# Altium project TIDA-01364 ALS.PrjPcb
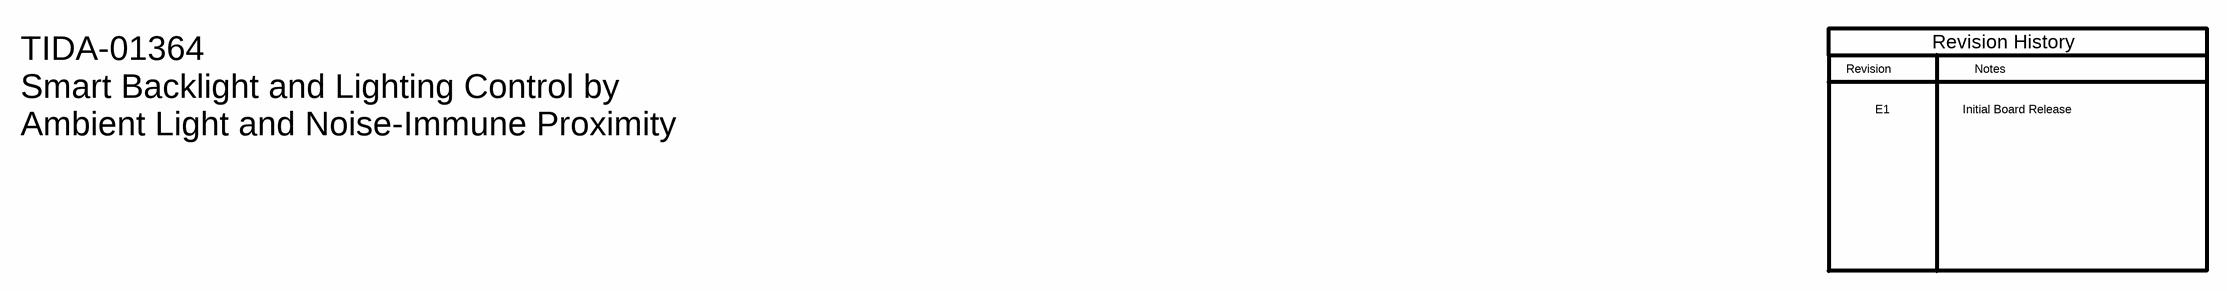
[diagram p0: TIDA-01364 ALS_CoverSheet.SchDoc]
TID: TIDA-01364; TechSupport: http://www.ti.com/support; SCH_Rev: A; PRJ_Title: TIDA-01364 Backlight Control and Proximity Sensing; PRJ_Number: TIDA-01364; PRJ_Engineer: Jarrod Krebs; PRJ_Customer: Public Release; PCB_Rev: A; EVM_Orderable: N/A; CopyrightYear: 2016
5 sheets, 139 parts. Net scope: global (net labels, ports and power ports of the same name join across sheets).
Board file: TIDA-01364 ALS_TID.PcbDoc
Sheets:
  TIDA-01364 ALS_CoverSheet.SchDoc
  TIDA-01364 ALS_Sheet1.SchDoc
  TIDA-01364 ALS_Sheet2.SchDoc
  TIDA-01364 ALS_Sheet3.SchDoc
  TIDA-01364 ALS_TID_Hardware.SchDoc

## Sheet TIDA-01364 ALS_CoverSheet.SchDoc: Cover Sheet
size 431 x 279 mm; Date: Not shown in title block; ApprovedBy: Not shown in title block; CheckedBy: Not shown in title block; Author: Not shown in title block; CompanyName: Not shown in title block; DrawnBy: Jarrod Krebs; Engineer: Not shown in title block; Organization: Not shown in title block; Address1: Not shown in title block; Address2: Not shown in title block; Address3: Not shown in title block; Address4: Not shown in title block; DocumentNumber: 1; Revision: Use project parameter SCH_Rev; SheetNumber: 1; SheetTotal: 5; PageSetup: Record=PageOptions¦CenterHorizontal=True¦CenterVertical=True¦PrintScale=1.00¦XCorrection=1.00¦YCorrection=1.00¦PrintKind=0¦BorderSize=5000000¦LeftOffset=0¦BottomOffset=0¦Orientation=2¦PaperLength=1000¦PaperWidth=1000¦Scale=100¦PaperSource=15¦PrintQuality=-3¦MediaType=1¦DitherType=10¦PrintScaleMode=1¦PaperKind=Letter¦PaperIndex=1

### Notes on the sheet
- Revision
- Notes
- Revision History
- E1
- Initial Board Release
- TIDA-01364
  Smart Backlight and Lighting Control by
  Ambient Light and Noise-Immune Proximity
  Sensor Reference Design

## Sheet TIDA-01364 ALS_Sheet1.SchDoc: Power and Display
size 431 x 279 mm; Date: Not shown in title block; ApprovedBy: Not shown in title block; CheckedBy: Not shown in title block; Author: Not shown in title block; CompanyName: Not shown in title block; DrawnBy: Jarrod Krebs; Engineer: Not shown in title block; Organization: Not shown in title block; Address1: Not shown in title block; Address2: Not shown in title block; Address3: Not shown in title block; Address4: Not shown in title block; DocumentNumber: 3; Revision: Use project parameter SCH_Rev; SheetNumber: 3; SheetTotal: 5; PageSetup: Record=PageOptions¦CenterHorizontal=True¦CenterVertical=True¦PrintScale=1.00¦XCorrection=1.00¦YCorrection=1.00¦PrintKind=0¦BorderSize=5000000¦LeftOffset=0¦BottomOffset=0¦Orientation=2¦PaperLength=1000¦PaperWidth=1000¦Scale=100¦PaperSource=15¦PrintQuality=-3¦MediaType=1¦DitherType=10¦PrintScaleMode=1¦PaperKind=Letter¦PaperIndex=1
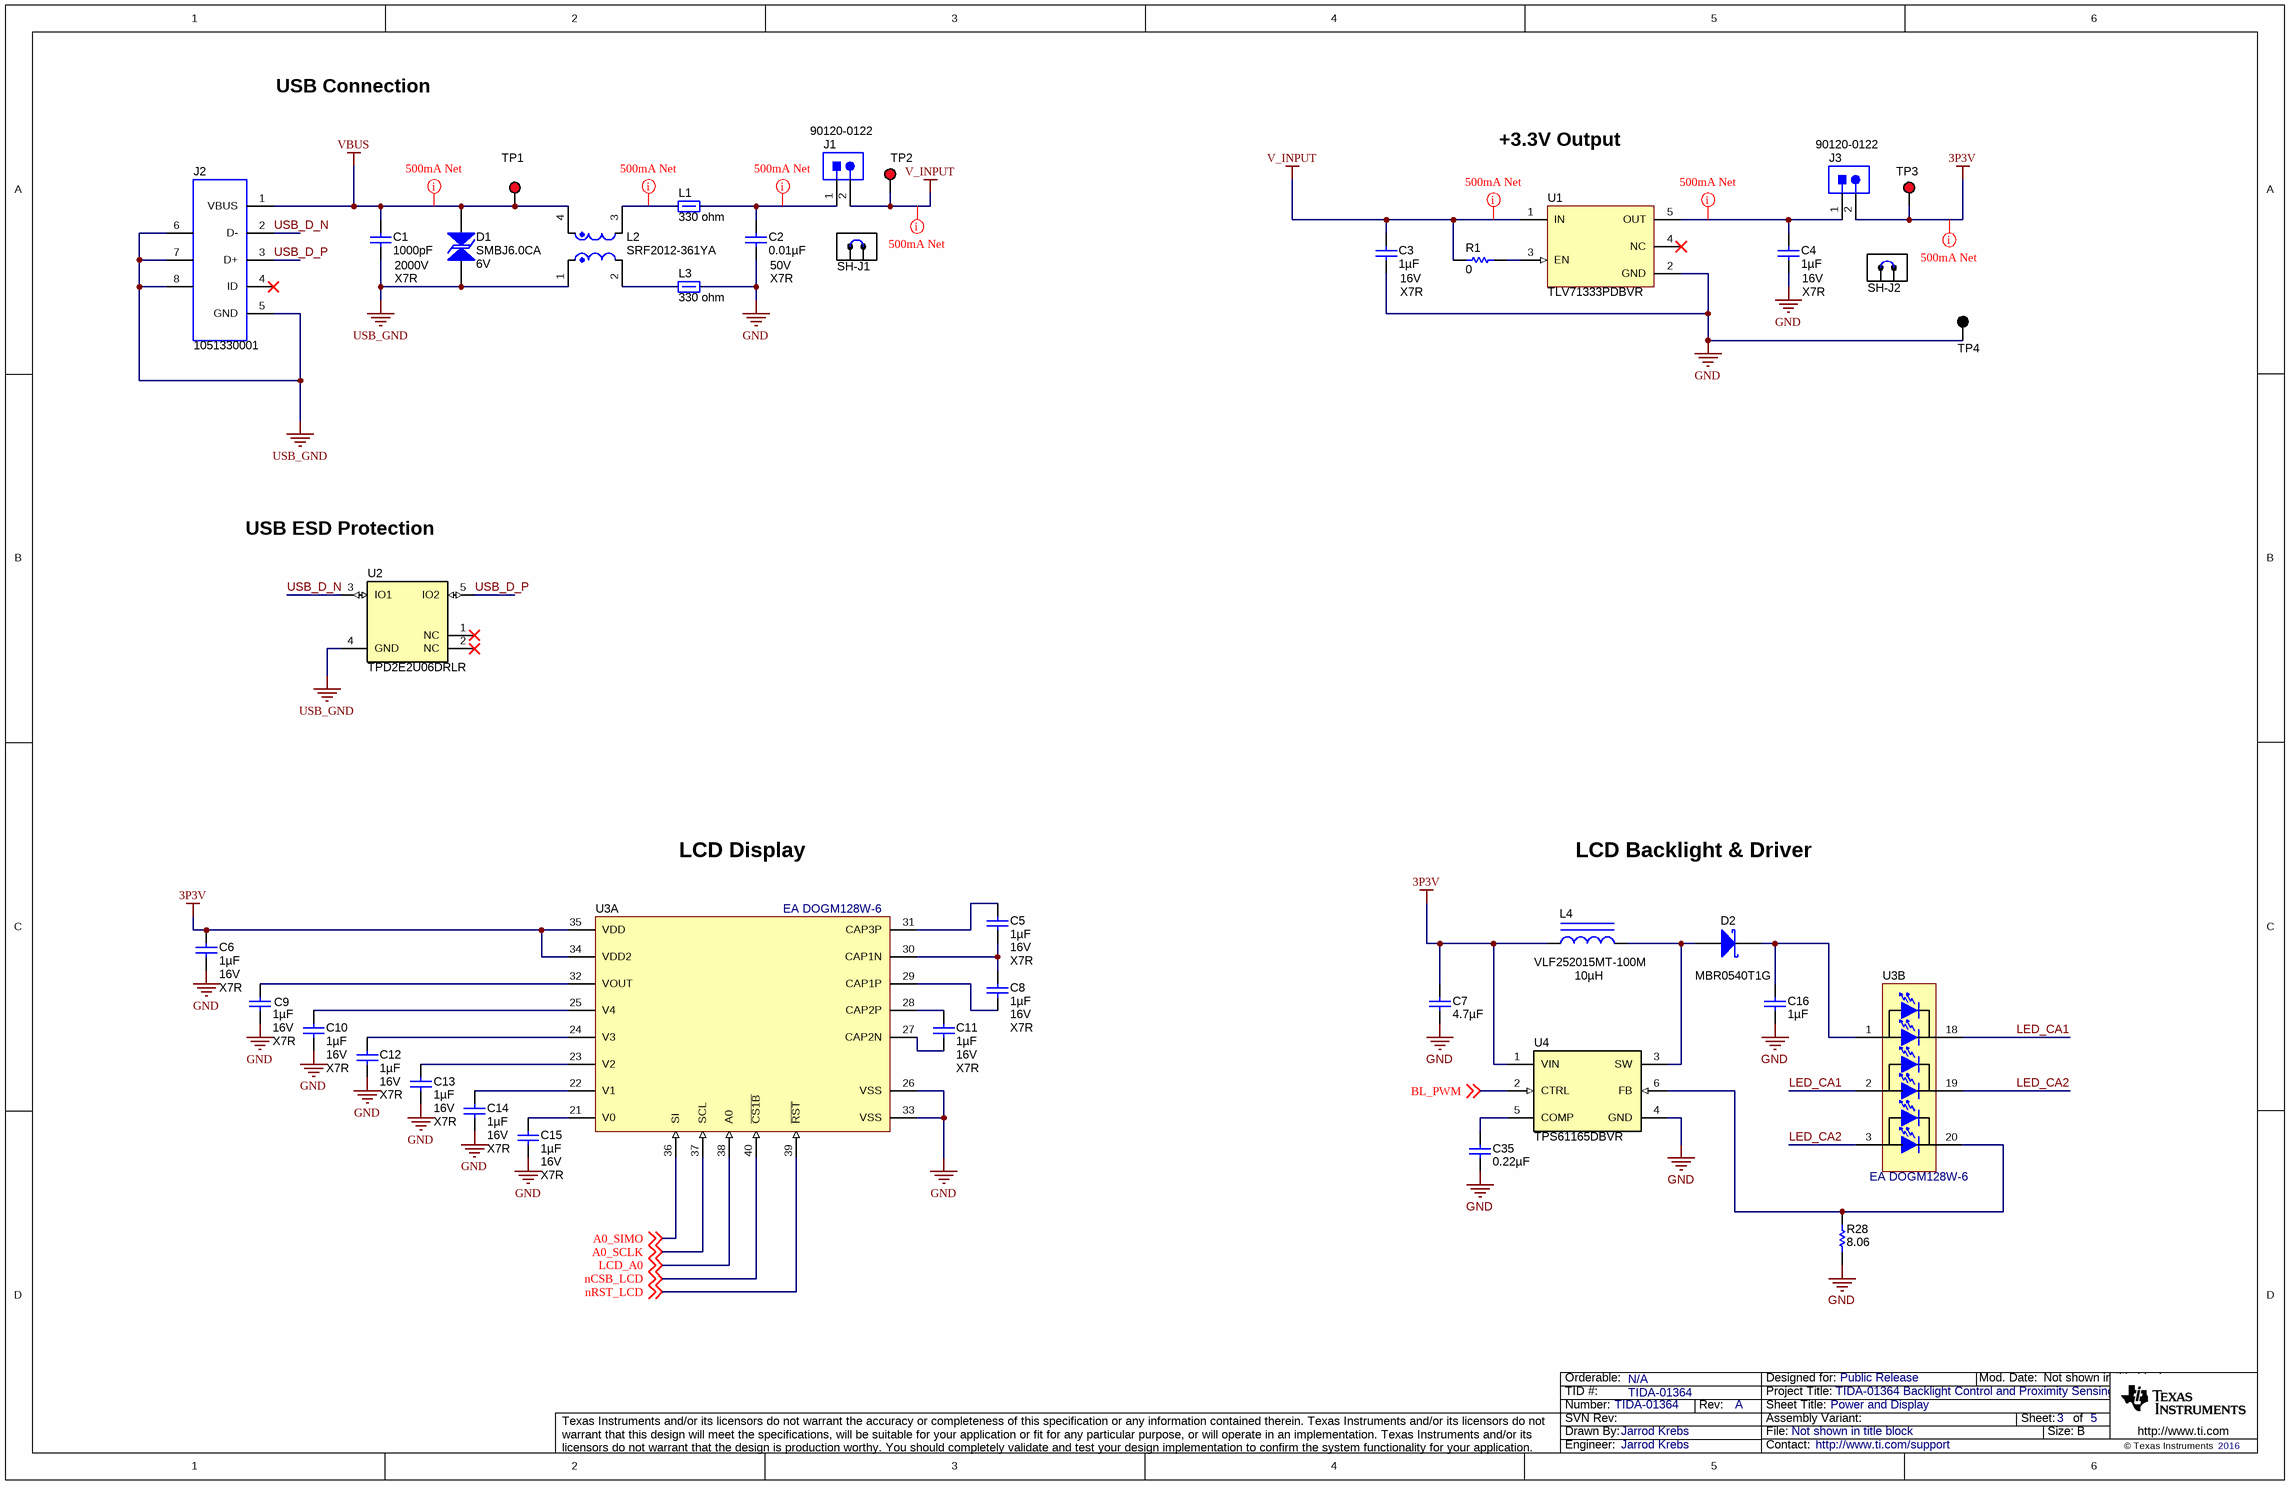
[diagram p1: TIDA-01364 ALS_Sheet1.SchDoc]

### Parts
C1  VDC_V: 2000V  TempCo: X7R  ValueDisplayed: 1000pF  [1206_190]  (hidden comment: 202R18W102KV4E)
C2  ValueDisplayed: 0.01µF  Value2: 50V  TempCo: X7R  [0805_HV]  (hidden comment: 08055C103JAT2A)
C3  ValueDisplayed: 1µF  Value2: 16V  TempCo: X7R  [0603]  (hidden comment: C1608X7R1C105K)
C4  ValueDisplayed: 1µF  Value2: 16V  TempCo: X7R  [0603]  (hidden comment: C1608X7R1C105K)
C5  ValueDisplayed: 1µF  Value2: 16V  TempCo: X7R  [0603]  (hidden comment: C1608X7R1C105K)
C6  ValueDisplayed: 1µF  Value2: 16V  TempCo: X7R  [0603]  (hidden comment: C1608X7R1C105K)
C7  ValueDisplayed: 4.7µF  [0603]  (hidden comment: GRM188R61A475ME15)
C8  ValueDisplayed: 1µF  Value2: 16V  TempCo: X7R  [0603]  (hidden comment: C1608X7R1C105K)
C9  ValueDisplayed: 1µF  Value2: 16V  TempCo: X7R  [0603]  (hidden comment: C1608X7R1C105K)
C10  ValueDisplayed: 1µF  Value2: 16V  TempCo: X7R  [0603]  (hidden comment: C1608X7R1C105K)
C11  ValueDisplayed: 1µF  Value2: 16V  TempCo: X7R  [0603]  (hidden comment: C1608X7R1C105K)
C12  ValueDisplayed: 1µF  Value2: 16V  TempCo: X7R  [0603]  (hidden comment: C1608X7R1C105K)
C13  ValueDisplayed: 1µF  Value2: 16V  TempCo: X7R  [0603]  (hidden comment: C1608X7R1C105K)
C14  ValueDisplayed: 1µF  Value2: 16V  TempCo: X7R  [0603]  (hidden comment: C1608X7R1C105K)
C15  ValueDisplayed: 1µF  Value2: 16V  TempCo: X7R  [0603]  (hidden comment: C1608X7R1C105K)
C16  ValueDisplayed: 1µF  [0603]  (hidden comment: GRM188R61E105KA12D)
C35  ValueDisplayed: 0.22µF  [0603]  (hidden comment: GRM188R61A224KA01D)
D1  SMBJ6.0CA  value 6V  [SMB]
D2  MBR0540T1G  [SOD-123]
J1  90120-0122  [CONN_90120-0122]
J2  1051330001  [Molex_1051330001]
J3  90120-0122  [CONN_90120-0122]
L1  value 330 ohm  [0603]  (hidden comment: BLM18SG331TN1D)
L2  SRF2012-361YA  [SRF2012A]
L3  value 330 ohm  [0603]  (hidden comment: BLM18SG331TN1D)
L4  VLF252015MT-100M  ValueDisplayed: 10µH  [IND_VLF252015]
R1  ValueDisplayed: 0  [0603]  (hidden comment: CRCW06030000Z0EA)
R28  ValueDisplayed: 8.06  [0603]  (hidden comment: CRCW06038R06FKEA)
SH-J1  2SN-BK-G  [2SN-BK-G]  (value not drawn)
SH-J2  2SN-BK-G  [2SN-BK-G]  (value not drawn)
TP1  5000  [Keystone5000]  (value not drawn)
TP2  5000  [Keystone5000]  (value not drawn)
TP3  5000  [Keystone5000]  (value not drawn)
TP4  5001  [Keystone5001]  (value not drawn)
U1  TLV71333PDBVR  [DBV0005A_N]
U2  TPD2E2U06DRLR  [DRL0005A]
U3  EA DOGM128W-6  [LCD-MODULE_EA DOGM128W-6]  (parts A,B of 2)
U4  TPS61165DBVR  [DBV0006A_N]

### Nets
3P3V: C6.1 C7.1 J3.2 L4.1 TP3.1 U3.34(VDD2) U3.35(VDD) U4.1(VIN)
GND: C2.2 C3.2 C4.2 C6.2 C7.2 C9.2 C10.2 C12.2 C13.2 C14.2 C15.2 C16.2 C35.2 L3.2 R28.1 TP4.1 U1.2(GND) U3.26(VSS) U3.33(VSS) U4.4(GND)
USB_GND: C1.2 D1.1 J2.5(GND) J2.6(Shield) J2.7(Shield) J2.8(Shield) L2.1 U2.4(GND)
V_INPUT: C3.1 J1.2 R1.1 TP2.1 U1.1(IN)
VBUS: C1.1 D1.2 J2.1(VBUS) L2.4 TP1.1
A0_SCLK: U3.37(SCL) ; off-sheet A0_SCLK
A0_SIMO: U3.36(SI) ; off-sheet A0_SIMO
BL_PWM: U4.2(CTRL) ; off-sheet BL_PWM
LCD_A0: U3.38(A0) ; off-sheet LCD_A0
LED_CA1: U3.2(A) U3.18(K)
LED_CA2: U3.3(A) U3.19(K)
nCSB_LCD: U3.40(~{CS1B}) ; off-sheet nCSB_LCD
nRST_LCD: U3.39(~{RST}) ; off-sheet nRST_LCD
USB_D_N: J2.2(D-) U2.3(IO1)
USB_D_P: J2.3(D+) U2.5(IO2)
NetC2_1: C2.1 J1.1 L1.2
NetC4_1: C4.1 J3.1 U1.5(OUT)
NetC5_1: C5.1 U3.31(CAP3P)
NetC5_2: C5.2 C8.1 U3.30(CAP1N)
NetC8_2: C8.2 U3.29(CAP1P)
NetC9_1: C9.1 U3.32(VOUT)
NetC10_1: C10.1 U3.25(V4)
NetC11_1: C11.1 U3.28(CAP2P)
NetC11_2: C11.2 U3.27(CAP2N)
NetC12_1: C12.1 U3.24(V3)
NetC13_1: C13.1 U3.23(V2)
NetC14_1: C14.1 U3.22(V1)
NetC15_1: C15.1 U3.21(V0)
NetC16_1: C16.1 D2.1(K) U3.1(A)
NetC35_1: C35.1 U4.5(COMP)
NetD2_2: D2.2(A) L4.2 U4.3(SW)
NetL1_1: L1.1 L2.3
NetL2_2: L2.2 L3.1
NetR1_2: R1.2 U1.3(EN)
NetR28_2: R28.2 U3.20(K) U4.6(FB)

Not connected (* = marked no-connect by the designer): J2 4(ID)*; U1 4(NC)*; U2 1(NC)* 2(NC)*

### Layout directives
rule Width Constraint [Pref Width = 25mil    Min Width = 5mil    Max Width = 100mil]: 3P3V, NetC2_1, NetC4_1, NetL1_1, V_INPUT, VBUS

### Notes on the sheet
- USB Connection
- +3.3V Output
- USB ESD Protection
- LCD Display
- LCD Backlight & Driver

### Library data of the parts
C1 = 202R18W102KV4E: CAP, CERM, 1000 pF, 2000 V, +/- 10%, X7R, 1206_190; Manufacturer: Johanson Technology; Polarized: N; CompType: Capacitor; Value: 1000pF; U/M: EA; Cap_F: 0.000000001; Tolerance_%: 10; Value1: Unknown; TaMin_C: -55; TaMax_C: 125
C2 = 08055C103JAT2A: CAP, CERM, 0.01 µF, 50 V, +/- 5%, X7R, 0805; Manufacturer: AVX; Polarized: N; CompType: Capacitor; Value: 0.01uF; U/M: EA; Cap_F: 0.00000001; Tolerance_%: 5; ESR_ohm: 0.078; Value1: 0.078 ohm; VDC_V: 50; TaMin_C: -55; TaMax_C: 125; Cap_Case: 0805
C3 C4 = C1608X7R1C105K: CAP, CERM, 1 µF, 16 V, +/- 10%, X7R, 0603; Manufacturer: TDK; Polarized: N; CompType: Capacitor; Value: 1uF; U/M: EA; Cap_F: 0.000001; Tolerance_%: 10; ESR_ohm: 0.0057; Value1: 0.0057 ohm; VDC_V: 16; TaMin_C: -55; TaMax_C: 125
C5 C6 C8-C15 = C1608X7R1C105K: CAP, CERM, 1uF, 16V, +/-10%, X7R, 0603; Manufacturer: TDK; Polarized: N; CompType: Capacitor; U/M: EA; Cap_F: 0.000001; Tolerance_%: 10; ESR_Ohm: 0.0057; Value1: 0.0057 ohm; VDC_V: 16; TaMin_C: -55; TaMax_C: 125
C7 = GRM188R61A475ME15: CAP, CERM, 4.7 µF, 10 V, +/- 20%, X5R, 0603; Manufacturer: MuRata; Polarized: N; CompType: Capacitor; Value: 4.7uF; U/M: EA; Cap_F: 0.0000047; Tolerance_%: 20; Value1: Unknown; VDC_V: 10; Value2: 10V; TaMin_C: -55; TaMax_C: 85; SizeArea_mm2: 1.28; SizeAreaWB_mm2: 4.68; SizeX_mm: 1.6; SizeY_mm: 0.8; SizeZ_mm: 1; AEC Category: Q200
C16 = GRM188R61E105KA12D: CAP, CERM, 1 µF, 25 V, +/- 10%, X5R, 0603; Manufacturer: MuRata; Polarized: N; CompType: Capacitor; Value: 1uF; U/M: EA; Cap_F: 0.000001; Tolerance_%: 10; Value1: Unknown; VDC_V: 25; Value2: 25V; TaMin_C: -55; TaMax_C: 85; SizeArea_mm2: 1.28; SizeAreaWB_mm2: 4.68; SizeX_mm: 1.6; SizeY_mm: 0.8; SizeZ_mm: 1; AEC Category: Q200
C35 = GRM188R61A224KA01D: CAP, CERM, 0.22 µF, 10 V, +/- 10%, X5R, 0603; Manufacturer: MuRata; Polarized: N; CompType: Capacitor; Value: 0.22uF; U/M: EA; Cap_F: 0.00000022; Tolerance_%: 10; Value1: Unknown; Value2: 10V; TaMin_C: -55; TaMax_C: 85; SizeArea_mm2: 1.28; SizeAreaWB_mm2: 4.68; SizeX_mm: 1.6; SizeY_mm: 0.8; SizeZ_mm: 1; AEC Category: Q200
D1 = SMBJ6.0CA: Diode, TVS, Bi, 6 V, 600 W, SMB; Manufacturer: Littelfuse; U/M: EA; Power_W: 600; Vr_V: 6; Value1: 600W; RJA_CperW: 100
D2 = MBR0540T1G: Diode, Schottky, 40 V, 0.5 A, SOD-123; Manufacturer: ON Semiconductor; U/M: EA; Vf_V: 0.51; Value: 40V; Value1: 0.5A; Value2: 0.51V; Io_A: 0.5; Vr_V: 40; TJmax_C: 150; RJC_CperW: 118; SizeAreaWB_mm2: 13.095; SizeArea_mm2: 6.545; SizeX_mm: 3.85; SizeY_mm: 1.7; SizeZ_mm: 1.35; AEC Category: Q101
J1 J3 = 90120-0122: Header, 100mil, 2x1, Tin, TH; Manufacturer: Molex; SymbolCreator: a0412235; U/M: EA
J2 = 1051330001: Connector, Receptacle, USB TYPE B, Vertical, TH; Manufacturer: Molex; SymbolCreator: Altium; U/M: EA
L1 L3 = BLM18SG331TN1D: Ferrite Bead, 330 ohm @ 100 MHz, 1.5 A, 0603; Manufacturer: MuRata; Imax_A: 1.5; DCR_ohm: 0.07; Value1: 0.07 ohm; Value2: 1.5A; ZTyp@100MHz_Ohm: 330
L2 = SRF2012-361YA: Inductor, Wirewound, Ferrite, , 0.3 A, 0.45 ohm, SMD; Manufacturer: Bourns; SymbolCreator: a0411947; Imax_A: 0.3; DCR_ohm: 0.45; Value2: 0.3A
L4 = VLF252015MT-100M: Inductor, Shielded, Ferrite, 10uH, 0.47A, 0.24 ohm, SMD; Manufacturer: TDK; Ind_H: 10.0E-6; Imax_A: 0.47; Irms: 0.94A @ 40C rise; Isat: 0.47A @ 30% inductance drop; DCR_ohm: 0.24
R1 = CRCW06030000Z0EA: RES, 0, 5%, 0.1 W, 0603; Manufacturer: Vishay-Dale; CompType: Resistor; Value: 0; Value_Code: 0000; Tolerance_%: 5; Power_W: 0.1; Value2: 0.1W; VDC_V: 75; TempCo: 200 ppm/C; EIA_Code: E24; U/M: EA
R28 = CRCW06038R06FKEA: RES, 8.06, 1%, 0.1 W, 0603; Manufacturer: Vishay-Dale; CompType: Resistor; Value: 8.06; Value_Code: 8R06; Tolerance_%: 1; Power_W: 0.1; Value2: 0.1W; VDC_V: 75; TempCo: 100 ppm/C; SizeArea_mm2: 1.28; SizeX_mm: 1.6; SizeY_mm: 0.8; EIA_Code: E96; U/M: EA; AEC Category: Q200
SH-J1 SH-J2 = 2SN-BK-G: Shunt, 2mm, Gold plated, Black; Manufacturer: Samtec; Value: 1x2; Note: You can "mate" this to a header by matching the designator.  i.e. use SH-J3 for header J3
TP1-TP3 = 5000: Test Point, Miniature, Red, TH; Manufacturer: Keystone; CompType: Test Point Loop; U/M: EA
TP4 = 5001: Test Point, Miniature, Black, TH; Manufacturer: Keystone; CompType: Test Point Loop; U/M: EA
U1 = TLV71333PDBV: Capacitor-Free, 150-mA, Low-Dropout Regulator with Foldback Current Limit for Portable Devices, DBV0005A; Alternate Manufacturer: None; Manufacturer: Texas Instruments; SymbolCreator: a0411947; CompType: IC; U/M: EA
U2 = TPD2E2U06DRLR: DUAL CHANNEL HIGH SPEED ESD PROTECTION DEVICE, DRL0005A; Manufacturer: Texas Instruments; SymbolCreator: a0411947; CompType: IC; U/M: EA; SizeArea_mm2: 2.56; SizeAreaWB_mm2: 6.76; SizeX_mm: 1.6; SizeZ_mm: 0.6
U3 = EA DOGM128W-6: Module, 128x64-pixel graphics display; Manufacturer: Electronic Assembly; SymbolCreator: a0799628
U4 = TPS61165DBVR: High Brightness White LED Driver, 3 to 18 V, -40 to 85 degC, 6-pin SOT23 (DBV6), Green (RoHS & no Sb/Br); Manufacturer: Texas Instruments; Alternate PartNumber: Equivalent; Dimming: TRUE; Iq(Typ)(mA): 1.5; Rating: Catalog; Switching Frequency(Max)(kHz): 1200; Topology: Boost; Vin(Max)(V): 18; Vin(Min)(V): 3

## Sheet TIDA-01364 ALS_Sheet2.SchDoc: MCU and EM Connector
size 431 x 279 mm; Date: Not shown in title block; ApprovedBy: Not shown in title block; CheckedBy: Not shown in title block; Author: Not shown in title block; CompanyName: Not shown in title block; DrawnBy: Jarrod Krebs; Engineer: Not shown in title block; Organization: Not shown in title block; Address1: Not shown in title block; Address2: Not shown in title block; Address3: Not shown in title block; Address4: Not shown in title block; DocumentNumber: 4; Revision: Use project parameter SCH_Rev; SheetNumber: 4; SheetTotal: 5; PageSetup: Record=PageOptions¦CenterHorizontal=True¦CenterVertical=True¦PrintScale=0.62¦XCorrection=1.00¦YCorrection=1.00¦PrintKind=0¦BorderSize=5000000¦LeftOffset=0¦BottomOffset=0¦Orientation=2¦PaperLength=1000¦PaperWidth=1000¦Scale=100¦PaperSource=15¦PrintQuality=-3¦MediaType=1¦DitherType=10¦PrintScaleMode=1¦PaperKind=Letter¦PaperIndex=1
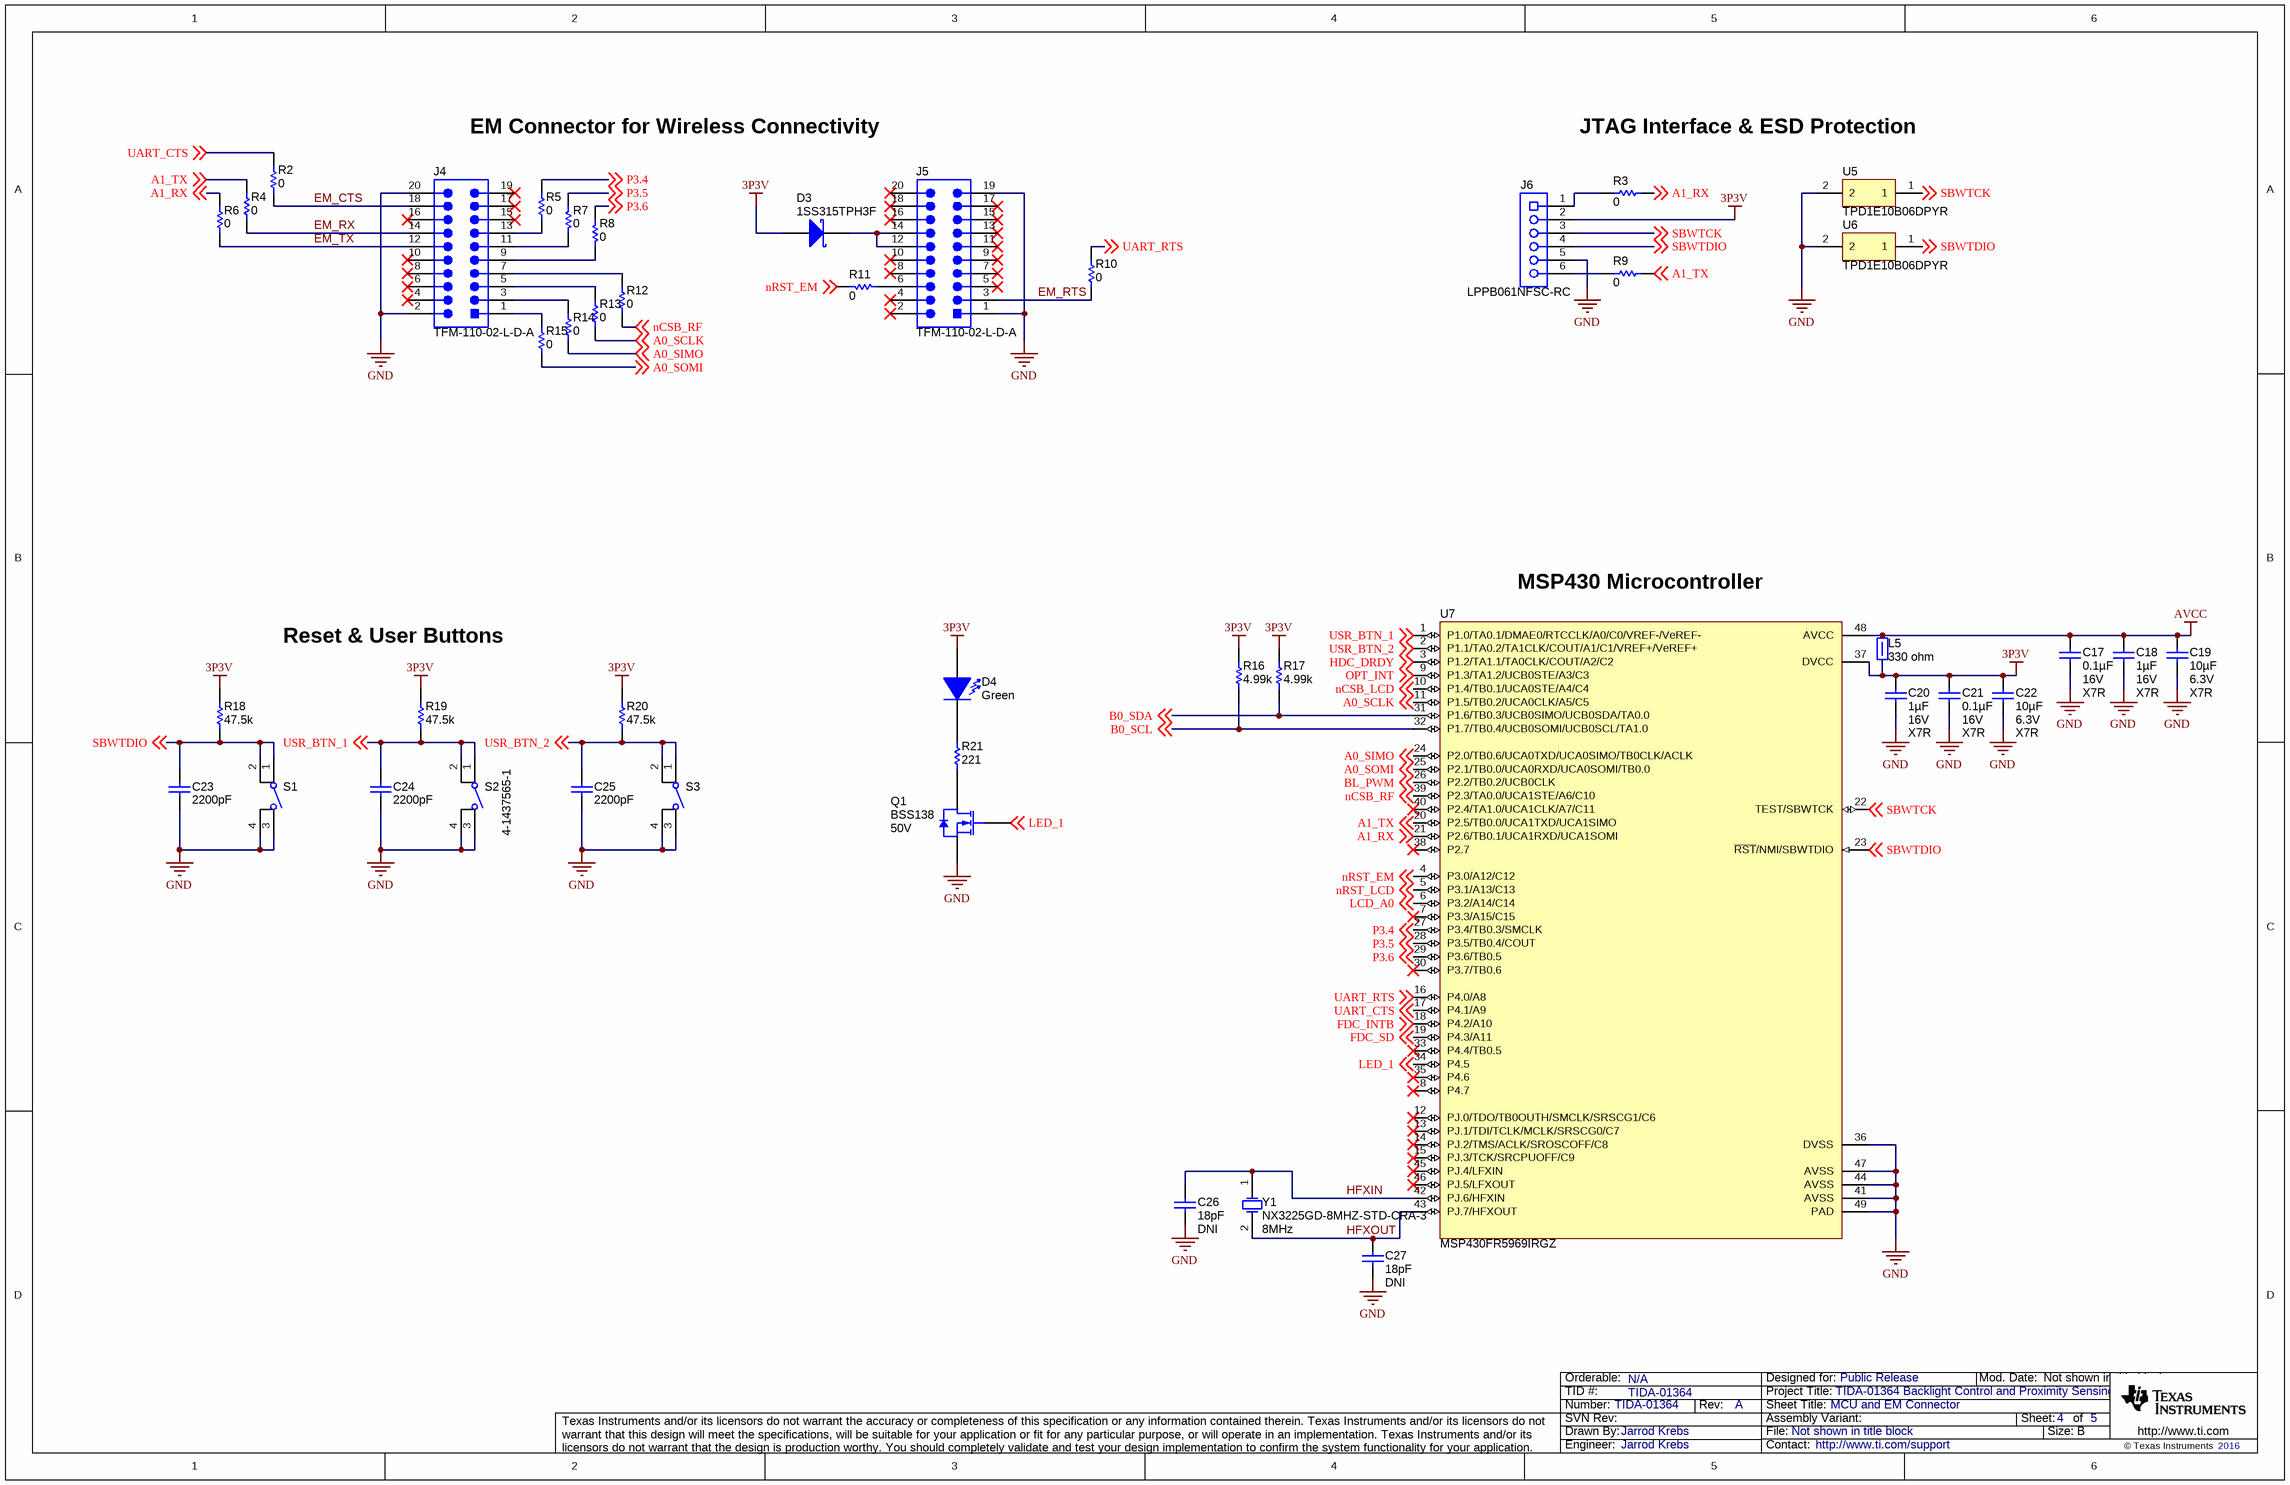
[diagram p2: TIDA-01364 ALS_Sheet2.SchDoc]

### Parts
C17  ValueDisplayed: 0.1µF  Value2: 16V  TempCo: X7R  [0402]  (hidden comment: GRM155R71C104KA88D)
C18  ValueDisplayed: 1µF  Value2: 16V  TempCo: X7R  [0603]  (hidden comment: C1608X7R1C105K)
C19  ValueDisplayed: 10µF  Value2: 6.3V  TempCo: X7R  [0805_HV]  (hidden comment: C2012X7R0J106M125AB)
C20  ValueDisplayed: 1µF  Value2: 16V  TempCo: X7R  [0603]  (hidden comment: C1608X7R1C105K)
C21  ValueDisplayed: 0.1µF  Value2: 16V  TempCo: X7R  [0402]  (hidden comment: GRM155R71C104KA88D)
C22  ValueDisplayed: 10µF  Value2: 6.3V  TempCo: X7R  [0805_HV]  (hidden comment: C2012X7R0J106M125AB)
C23  ValueDisplayed: 2200pF  [0402]  (hidden comment: CGA2B2X7R1H222K050BA)
C24  ValueDisplayed: 2200pF  [0402]  (hidden comment: CGA2B2X7R1H222K050BA)
C25  ValueDisplayed: 2200pF  [0402]  (hidden comment: CGA2B2X7R1H222K050BA)
C26  ValueDisplayed: 18pF  [0603]  (hidden comment: GRM1885C2A180JA01D)
C27  ValueDisplayed: 18pF  [0603]  (hidden comment: GRM1885C2A180JA01D)
D3  1SS315TPH3F  [sod-323]
D4  value Green  [SML-P1_GREEN]  (hidden comment: SML-P12PTT86)
J4  TFM-110-02-L-D-A  [Samtec_TFM-110-02-L-D-A]
J5  TFM-110-02-L-D-A  [Samtec_TFM-110-02-L-D-A]
J6  LPPB061NFSC-RC  [Sullins_LPPB061NFSC-RC]
L5  value 330 ohm  [0603]  (hidden comment: BLM18SG331TN1D)
Q1  BSS138  value 50V  [SOT-23]
R2  value 0  [0402]  (hidden comment: CRCW04020000Z0ED)
R3  value 0  [0402]  (hidden comment: CRCW04020000Z0ED)
R4  value 0  [0402]  (hidden comment: CRCW04020000Z0ED)
R5  value 0  [0402]  (hidden comment: CRCW04020000Z0ED)
R6  value 0  [0402]  (hidden comment: CRCW04020000Z0ED)
R7  value 0  [0402]  (hidden comment: CRCW04020000Z0ED)
R8  value 0  [0402]  (hidden comment: CRCW04020000Z0ED)
R9  value 0  [0402]  (hidden comment: CRCW04020000Z0ED)
R10  value 0  [0402]  (hidden comment: CRCW04020000Z0ED)
R11  value 0  [0402]  (hidden comment: CRCW04020000Z0ED)
R12  value 0  [0402]  (hidden comment: CRCW04020000Z0ED)
R13  value 0  [0402]  (hidden comment: CRCW04020000Z0ED)
R14  value 0  [0402]  (hidden comment: CRCW04020000Z0ED)
R15  value 0  [0402]  (hidden comment: CRCW04020000Z0ED)
R16  value 4.99k  [0402]  (hidden comment: CRCW04024K99FKED)
R17  value 4.99k  [0402]  (hidden comment: CRCW04024K99FKED)
R18  ValueDisplayed: 47.5k  [0402]  (hidden comment: CRCW040247K5FKED)
R19  ValueDisplayed: 47.5k  [0402]  (hidden comment: CRCW040247K5FKED)
R20  ValueDisplayed: 47.5k  [0402]  (hidden comment: CRCW040247K5FKED)
R21  value 221  [0402]  (hidden comment: CRCW0402221RFKED)
S1  4-1437565-1  [SW_FSM4JSMA]  (value not drawn)
S2  4-1437565-1  [SW_FSM4JSMA]
S3  4-1437565-1  [SW_FSM4JSMA]  (value not drawn)
U5  TPD1E10B06DPYR  [DPY0002A]
U6  TPD1E10B06DPYR  [DPY0002A]
U7  MSP430FR5969IRGZ  [RGZ0048B]
Y1  NX3225GD-8MHZ-STD-CRA-3  Frequency: 8MHz  [NDK_NX3225GD]

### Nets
3P3V: C20.2 C21.2 C22.1 D3.2(A) D4.2(A) J6.2 L5.1 R16.2 R17.2 R18.2 R19.2 R20.2 U7.37(DVCC)
AVCC: C17.2 C18.2 C19.1 L5.2 U7.48(AVCC)
GND: C17.1 C18.1 C19.2 C20.1 C21.1 C22.2 C23.1 C24.1 C25.1 C26.2 C27.2 J4.2 J4.20 J5.1 J5.19 J6.5 Q1.2(S) S1.3 S1.4 S2.3 S2.4 S3.3 S3.4 U5.2 U6.2 U7.36(DVSS) U7.41(AVSS) U7.44(AVSS) U7.47(AVSS) U7.49(PAD)
A0_SCLK: R13.2 U7.11(P1.5/TB0.2/UCA0CLK/A5/C5) ; off-sheet A0_SCLK
A0_SIMO: R14.2 U7.24(P2.0/TB0.6/UCA0TXD/UCA0SIMO/TB0CLK/ACLK) ; off-sheet A0_SIMO
A0_SOMI: R15.1 U7.25(P2.1/TB0.0/UCA0RXD/UCA0SOMI/TB0.0) ; off-sheet A0_SOMI
A1_RX: R3.1 R6.1 U7.21(P2.6/TB0.1/UCA1RXD/UCA1SOMI) ; off-sheet A1_RX
A1_TX: R4.1 R9.1 U7.20(P2.5/TB0.0/UCA1TXD/UCA1SIMO) ; off-sheet A1_TX
B0_SCL: R16.1 U7.32(P1.7/TB0.4/UCB0SOMI/UCB0SCL/TA1.0) ; off-sheet B0_SCL
B0_SDA: R17.1 U7.31(P1.6/TB0.3/UCB0SIMO/UCB0SDA/TA0.0) ; off-sheet B0_SDA
BL_PWM: U7.26(P2.2/TB0.2/UCB0CLK) ; off-sheet BL_PWM
EM_CTS: J4.18 R2.1
EM_RTS: J5.3 R10.2
EM_RX: J4.14 R4.2
EM_TX: J4.12 R6.2
FDC_INTB: U7.18(P4.2/A10) ; off-sheet FDC_INTB
FDC_SD: U7.19(P4.3/A11) ; off-sheet FDC_SD
HDC_DRDY: U7.3(P1.2/TA1.1/TA0CLK/COUT/A2/C2) ; off-sheet HDC_DRDY
HFXIN: C26.1 U7.42(PJ.6/HFXIN) Y1.1(OSC1)
HFXOUT: C27.1 U7.43(PJ.7/HFXOUT) Y1.2(OSC2)
LCD_A0: U7.6(P3.2/A14/C14) ; off-sheet LCD_A0
LED_1: Q1.1(G) U7.34(P4.5) ; off-sheet LED_1
nCSB_LCD: U7.10(P1.4/TB0.1/UCA0STE/A4/C4) ; off-sheet nCSB_LCD
nCSB_RF: R12.2 U7.39(P2.3/TA0.0/UCA1STE/A6/C10) ; off-sheet nCSB_RF
nRST_EM: R11.2 U7.4(P3.0/A12/C12) ; off-sheet nRST_EM
nRST_LCD: U7.5(P3.1/A13/C13) ; off-sheet nRST_LCD
OPT_INT: U7.9(P1.3/TA1.2/UCB0STE/A3/C3) ; off-sheet OPT_INT
P3.4: R5.2 U7.27(P3.4/TB0.3/SMCLK) ; off-sheet P3.4
P3.5: R7.1 U7.28(P3.5/TB0.4/COUT) ; off-sheet P3.5
P3.6: R8.1 U7.29(P3.6/TB0.5) ; off-sheet P3.6
SBWTCK: J6.3 U5.1 U7.22(TEST/SBWTCK) ; off-sheet SBWTCK
SBWTDIO: C23.2 J6.4 R18.1 S1.1 S1.2 U6.1 U7.23(~{RST}/NMI/SBWTDIO) ; off-sheet SBWTDIO
UART_CTS: R2.2 U7.17(P4.1/A9) ; off-sheet UART_CTS
UART_RTS: R10.1 U7.16(P4.0/A8) ; off-sheet UART_RTS
USR_BTN_1: C24.2 R19.1 S2.1 S2.2 U7.1(P1.0/TA0.1/DMAE0/RTCCLK/A0/C0/VREF-/VeREF-) ; off-sheet USR_BTN_1
USR_BTN_2: C25.2 R20.1 S3.1 S3.2 U7.2(P1.1/TA0.2/TA1CLK/COUT/A1/C1/VREF+/VeREF+) ; off-sheet USR_BTN_2
NetD3_1: D3.1(K) J5.12 J5.14
NetD4_1: D4.1(K) R21.2
NetJ4_1: J4.1 R15.2
NetJ4_3: J4.3 R14.1
NetJ4_5: J4.5 R13.1
NetJ4_7: J4.7 R12.1
NetJ4_9: J4.9 R8.2
NetJ4_11: J4.11 R7.2
NetJ4_13: J4.13 R5.1
NetJ5_6: J5.6 R11.1
NetJ6_1: J6.1 R3.2
NetJ6_6: J6.6 R9.2
NetQ1_3: Q1.3(D) R21.1

Not connected (* = marked no-connect by the designer): J4 4* 6* 8* 10* 15* 16* 17* 19*; J5 2* 4* 5* 7* 8* 9* 10* 11* 13* 15* 16* 17* 18* 20*; U7 7(P3.3/A15/C15)* 8(P4.7)* 12(PJ.0/TDO/TB0OUTH/SMCLK/SRSCG1/C6)* 13(PJ.1/TDI/TCLK/MCLK/SRSCG0/C7)* 14(PJ.2/TMS/ACLK/SROSCOFF/C8)* 15(PJ.3/TCK/SRCPUOFF/C9)* 30(P3.7/TB0.6)* 33(P4.4/TB0.5)* 35(P4.6)* 38(P2.7)* 40(P2.4/TA1.0/UCA1CLK/A7/C11)* 45(PJ.4/LFXIN)* 46(PJ.5/LFXOUT)*

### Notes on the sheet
- EM Connector for Wireless Connectivity
- JTAG Interface & ESD Protection
- Reset & User Buttons
- (near U7) MSP430 Microcontroller

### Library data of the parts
C17 C21 = GRM155R71C104KA88D: CAP, CERM, 0.1uF, 16V, +/-10%, X7R, 0402; Manufacturer: MuRata; Polarized: N; CompType: Capacitor; U/M: EA; Cap_F: 0.0000001; Tolerance_%: 10; Value1: Unknown; VDC_V: 16; TaMin_C: -55; TaMax_C: 125
C18 C20 = C1608X7R1C105K: as C5 on sheet TIDA-01364 ALS_Sheet1
C19 C22 = C2012X7R0J106M125AB: CAP, CERM, 10 µF, 6.3 V, +/- 20%, X7R, 0805; Manufacturer: TDK; Polarized: N; CompType: Capacitor; Value: 10uF; U/M: EA; Cap_F: 0.00001; Tolerance_%: 20; Value1: Unknown; VDC_V: 6.3; TaMin_C: -55; TaMax_C: 125; Cap_Case: 0805
C23-C25 = CGA2B2X7R1H222K050BA: CAP, CERM, 2200 pF, 50 V, +/- 10%, X7R, AEC-Q200 Grade 1, 0402; Manufacturer: TDK; Polarized: N; CompType: Capacitor; Value: 2200pF; U/M: EA; Cap_F: 0.0000000022; Tolerance_%: 10; ESR_ohm: 1.07794; Value1: 1.07794 ohm; VDC_V: 50; Value2: 50V; IRMS_A: 0.264071; TaMin_C: -55; TaMax_C: 125; SizeArea_mm2: 0.5; SizeAreaWB_mm2: 3; SizeX_mm: 1; SizeZ_mm: 0.6; AEC Category: Q200; AEC Qualified: Y
C26 C27 = GRM1885C2A180JA01D: CAP, CERM, 18pF, 100V, +/-5%, C0G/NP0, 0603; Manufacturer: MuRata; Polarized: N; CompType: Capacitor; U/M: EA; Cap_F: 0.000000000018; Tolerance_%: 5; Value1: Unknown; VDC_V: 100; TaMin_C: -55; TaMax_C: 125
D3 = 1SS315TPH3F: Diode, Schottky, 5V, 0.03A, SOD-323; Manufacturer: Toshiba; U/M: EA; Vf_V: 0.38; Value2: 0.38V; Io_A: 0.03; Vr_V: 5; TJmax_C: 125
D4 = SML-P12PTT86: LED, Green, SMD; Manufacturer: Rohm; Type: AlInGaP; Vf_V: 2.2; Value2: 2.2V; Io_A: 0.02; Value1: W; U/M: EA
J4 J5 = TFM-110-02-L-D-A: Straight Low Profile Header, 10x2 Position,1.27 mm Pitch, SMT; Manufacturer: Samtec; SymbolCreator: a0412235; U/M: EA
J6 = LPPB061NFSC-RC: Receptacle, 1.27mm, 6x1, Gold, SMT; Manufacturer: Sullins Connector Solutions; SymbolCreator: a0411947; U/M: EA
L5 = BLM18SG331TN1D: 1.5A Ferrite Bead, 330 ohm @ 100MHz, SMD; Manufacturer: MuRata; Imax_A: 1.5; DCR_ohm: 0.07; Value1: 0.07 ohm; ZTyp@100MHz_Ohm: 330; U/M: EA
Q1 = BSS138: MOSFET, N-CH, 50V, 0.22A, SOT-23; Manufacturer: Fairchild Semiconductor; Alternate Manufacturer: None; U/M: EA; ChType: N; VdsMax_V: 50; Value1: 6 ohm; Rdson45_Ohm: 6; Value2: 1.7 nC; QgTyp_nC: 1.7; Vgs_V: 20; IdsMax_A: 0.22
R2-R15 = CRCW04020000Z0ED: RES, 0 ohm, 5%, 0.063W, 0402; Manufacturer: Vishay-Dale; CompType: Resistor; Value_Code: 0000; Tolerance_%: 5; Power_W: 0.063; VDC_V: 50; TempCo: 200 ppm/C; EIA_Code: E24; U/M: EA
R16 R17 = CRCW04024K99FKED: RES, 4.99k ohm, 1%, 0.063W, 0402; Manufacturer: Vishay-Dale; CompType: Resistor; Res_ohm: 4990; Value_Code: 4k99; Tolerance_%: 1; Power_W: 0.063; VDC_V: 50; TempCo: 100 ppm/C; EIA_Code: E96; U/M: EA
R18-R20 = CRCW040247K5FKED: RES, 47.5 k, 1%, 0.063 W, 0402; Manufacturer: Vishay-Dale; CompType: Resistor; Res_ohm: 47500; Value: 47.5k; Value_Code: 47k5; Tolerance_%: 1; Power_W: 0.063; Value2: 0.063W; VDC_V: 50; TempCo: 100 ppm/C; EIA_Code: E96; U/M: EA
R21 = CRCW0402221RFKED: RES, 221 ohm, 1%, 0.063W, 0402; Manufacturer: Vishay-Dale; CompType: Resistor; Value_Code: 221R; Tolerance_%: 1; Power_W: 0.063; VDC_V: 50; TempCo: 100 ppm/C; EIA_Code: E96; U/M: EA
S1-S3 = 4-1437565-1: Switch, Tactile, SPST-NO, 0.05A, 12V, SMT; Manufacturer: TE Connectivity; SymbolCreator: a0412235; VDC_V: 12; SwitchFunction: Off-Mom; PositionCount: 1; CurrentRating_mA: 50
U5 U6 = TPD1E10B06DPYR: ESD in 0402 Package with 10 pF Capacitance and 6 V Breakdown, 1 Channel, -40 to +125 degC, 2-pin X2SON (DPY), Green (RoHS & no Sb/Br); Manufacturer: Texas Instruments; Alternate Manufacturer: None; Alternate PartNumber: Equivalent; Breakdown Voltage(Min)(V): 6; Eco-Plan: TBD; IEC 61000-4-2 Air-Gap(+/- kV): 30; IO Capacitance(Typ)(pF): 10; SubFamily: ESD Solution
U7 = MSP430FR5969IRGZ: Mixed Signal Microcontroller, RGZ0048B; Alternate Manufacturer: None; Manufacturer: Texas Instruments; SymbolCreator: a0411947; CompType: IC; U/M: EA
Y1 = NX3225GD-8MHZ-STD-CRA-3: Crystal, 8MHz, 5pF, SMD; Manufacturer: NDK; SymbolCreator: a0412235; U/M: EA; TaMin_C: -40; TaMax_C: 150; Frequency Stability: ±150ppm

## Sheet TIDA-01364 ALS_Sheet3.SchDoc: Sensors
size 431 x 279 mm; Date: Not shown in title block; ApprovedBy: Not shown in title block; CheckedBy: Not shown in title block; Author: Not shown in title block; CompanyName: Not shown in title block; DrawnBy: Jarrod Krebs; Engineer: Not shown in title block; Organization: Not shown in title block; Address1: Not shown in title block; Address2: Not shown in title block; Address3: Not shown in title block; Address4: Not shown in title block; DocumentNumber: 5; Revision: Use project parameter SCH_Rev; SheetNumber: 5; SheetTotal: 5; PageSetup: Record=PageOptions¦CenterHorizontal=True¦CenterVertical=True¦PrintScale=0.62¦XCorrection=1.00¦YCorrection=1.00¦PrintKind=0¦BorderSize=5000000¦LeftOffset=0¦BottomOffset=0¦Orientation=2¦PaperLength=1000¦PaperWidth=1000¦Scale=100¦PaperSource=15¦PrintQuality=-3¦MediaType=1¦DitherType=10¦PrintScaleMode=1¦PaperKind=Letter¦PaperIndex=1
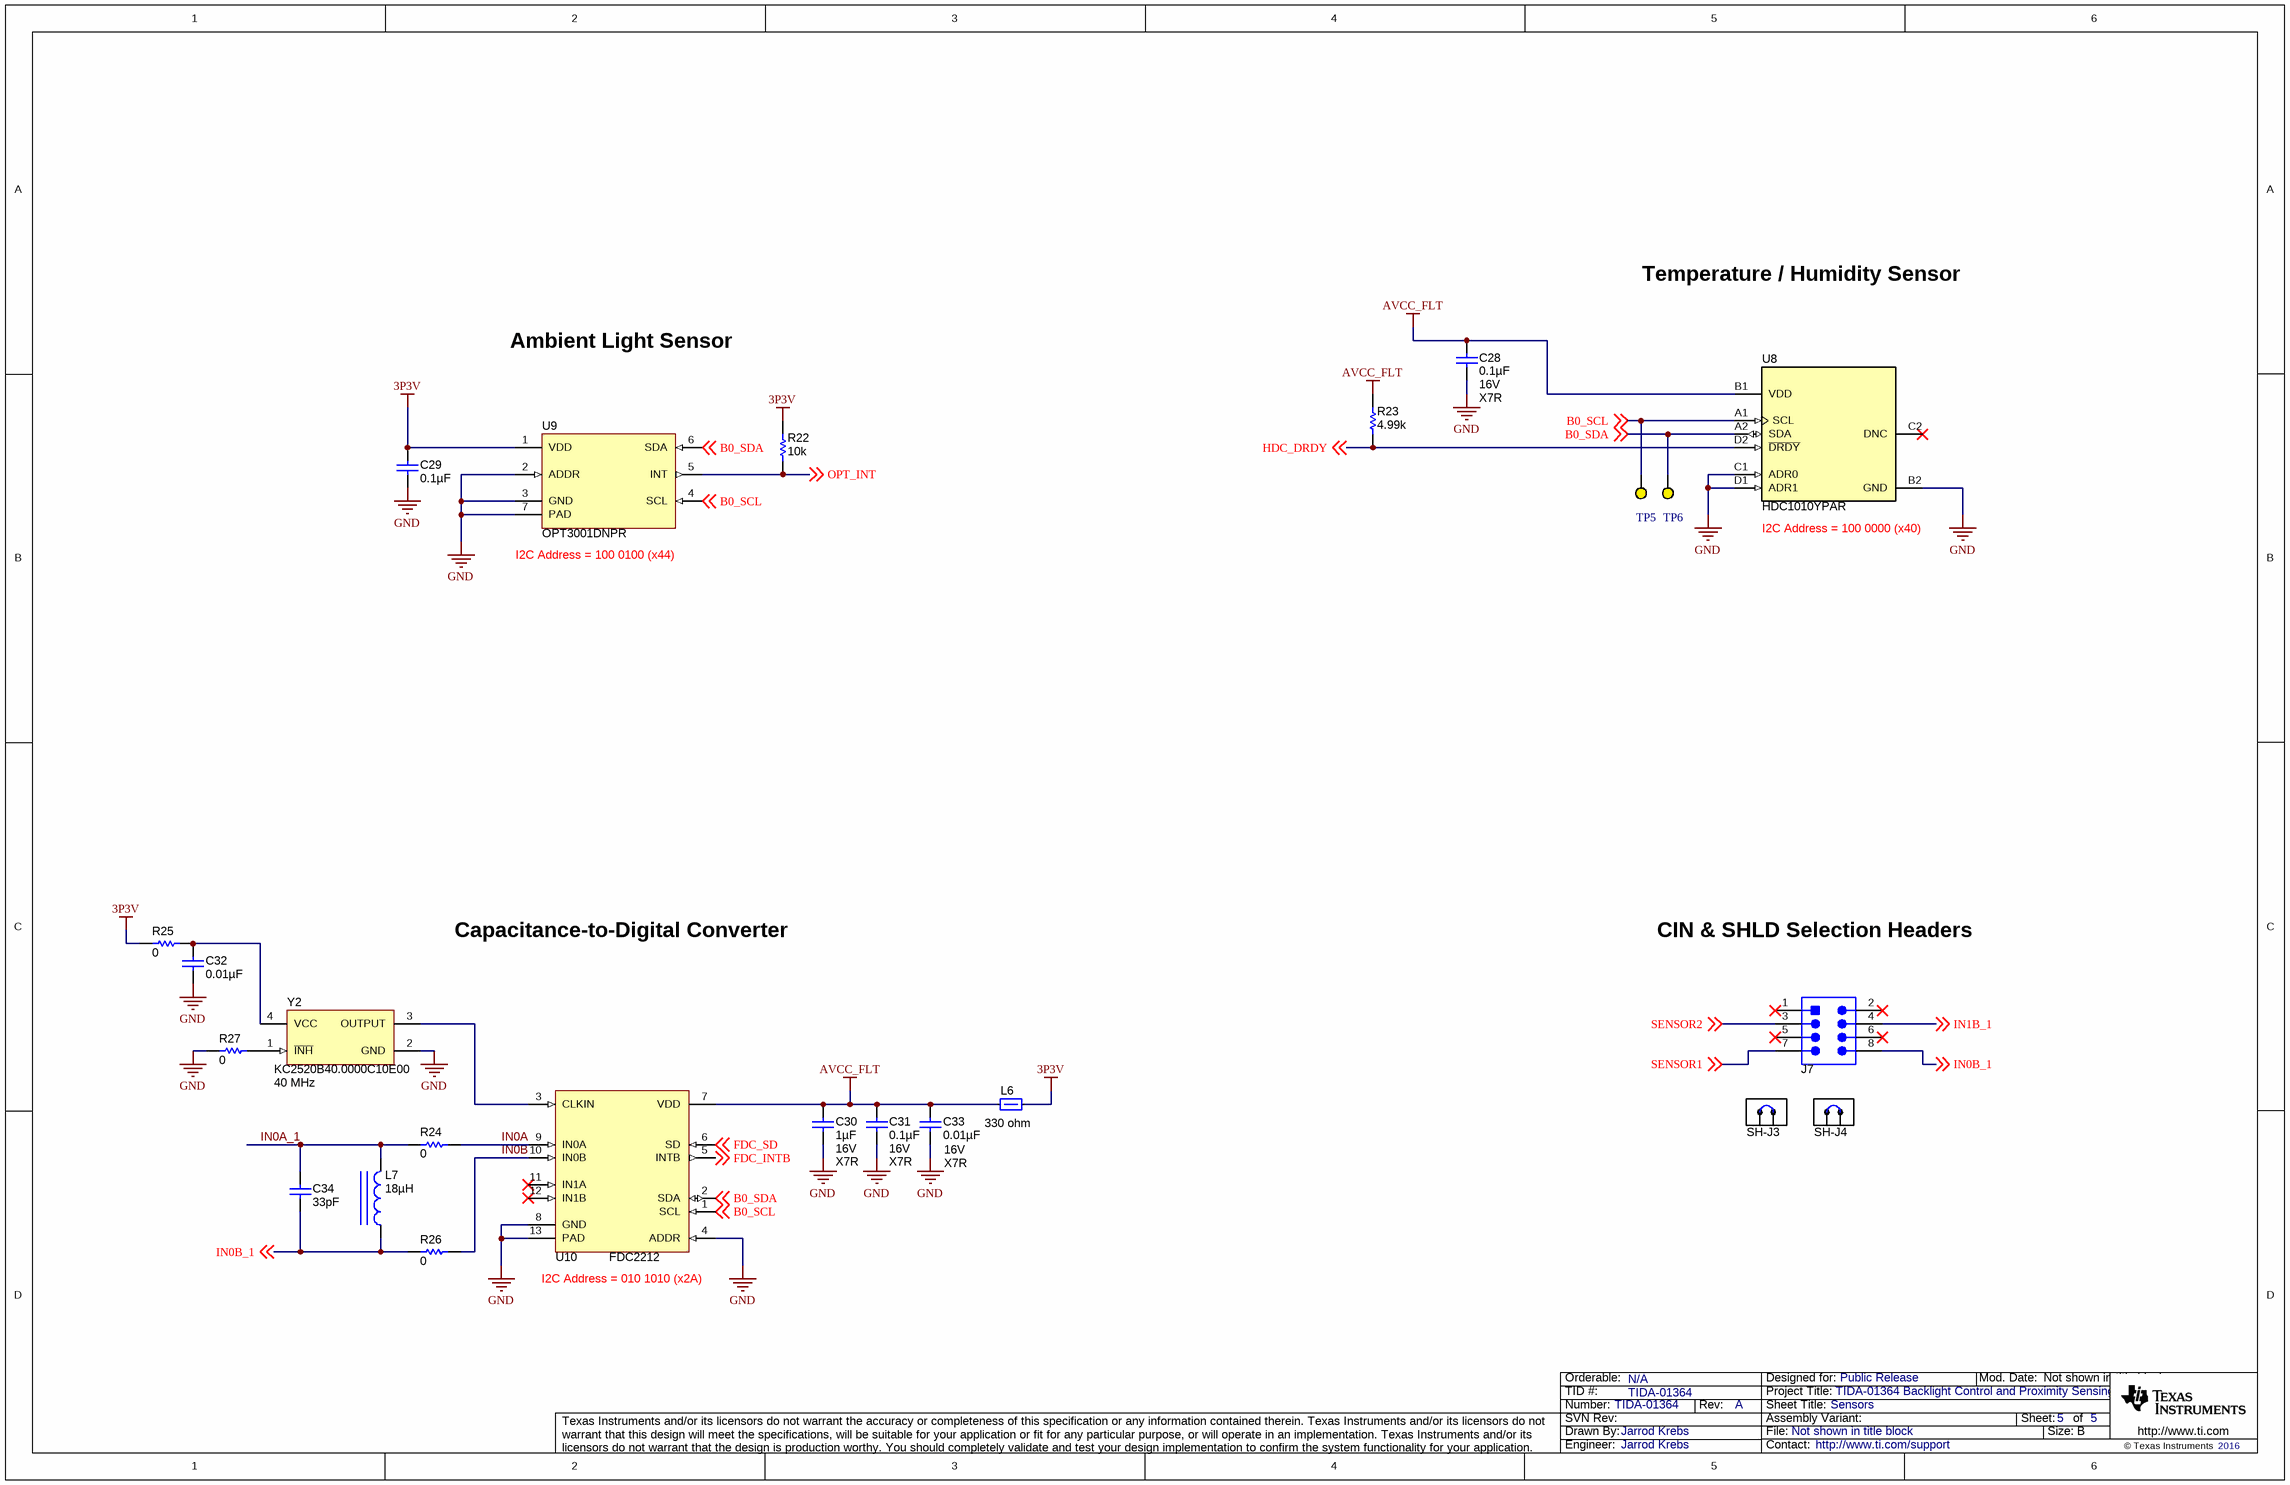
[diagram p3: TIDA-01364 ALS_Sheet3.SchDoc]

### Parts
C28  ValueDisplayed: 0.1µF  Value2: 16V  TempCo: X7R  [0402]  (hidden comment: GRM155R71C104KA88D)
C29  ValueDisplayed: 0.1µF  [0603]  (hidden comment: 06033C104JAT2A)
C30  ValueDisplayed: 1µF  Value2: 16V  TempCo: X7R  [0603]  (hidden comment: C1608X7R1C105K)
C31  ValueDisplayed: 0.1µF  Value2: 16V  TempCo: X7R  [0402]  (hidden comment: GRM155R71C104KA88D)
C32  ValueDisplayed: 0.01µF  [0603]  (hidden comment: GRM188R71E103KA01D)
C33  ValueDisplayed: 0.01µF  Value2: 16V  TempCo: X7R  [0402]  (hidden comment: GRM155R71C103KA01D)
C34  ValueDisplayed: 33pF  [0603]  (hidden comment: GRM1885C2A330JA01D)
J7  0015910080  [Molex_0015910080]  (value not drawn)
L6  value 330 ohm  [0603]  (hidden comment: BLM18SG331TN1D)
L7  ValueDisplayed: 18µH  [CMH322522]  (hidden comment: CMH322522-180KL)
R22  ValueDisplayed: 10k  [0402]  (hidden comment: CRCW040210K0JNED)
R23  ValueDisplayed: 4.99k  [0402]  (hidden comment: CRCW04024K99FKED)
R24  ValueDisplayed: 0  [0402]  (hidden comment: CRCW04020000Z0ED)
R25  ValueDisplayed: 0  [0402]  (hidden comment: CRCW04020000Z0ED)
R26  ValueDisplayed: 0  [0402]  (hidden comment: CRCW04020000Z0ED)
R27  ValueDisplayed: 0  [0402]  (hidden comment: CRCW04020000Z0ED)
SH-J3  2SN-BK-G  [2SN-BK-G]  (value not drawn)
SH-J4  2SN-BK-G  [2SN-BK-G]  (value not drawn)
TP5  5004  [Keystone5004]  (value not drawn)
TP6  5004  [Keystone5004]  (value not drawn)
U8  HDC1010YPAR  [YPA0008AGAE]
U9  OPT3001DNPR  [DNP0006A]
U10  Alternate PartNumber: FDC2212  [DNT0012B]  (hidden comment: FDC2212DNTR)
Y2  Frequency: 40 MHz  [AVX_KC2520B]  (hidden comment: KC2520B40.0000C10E00)

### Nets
3P3V: C29.1 L6.2 R22.2 R25.2 U9.1(VDD)
AVCC_FLT: C28.2 C30.1 C31.2 C33.1 L6.1 R23.2 U8.B1(VDD) U10.7(VDD)
GND: C28.1 C29.2 C30.2 C31.1 C32.2 C33.2 R27.2 U8.B2(GND) U8.C1(ADR0) U8.D1(ADR1) U9.2(ADDR) U9.3(GND) U9.7(PAD) U10.4(ADDR) U10.8(GND) U10.13(PAD) Y2.2(GND)
B0_SCL: TP5.1 U8.A1(SCL) U9.4(SCL) U10.1(SCL) ; off-sheet B0_SCL
B0_SDA: TP6.1 U8.A2(SDA) U9.6(SDA) U10.2(SDA) ; off-sheet B0_SDA
FDC_INTB: U10.5(INTB) ; off-sheet FDC_INTB
FDC_SD: U10.6(SD) ; off-sheet FDC_SD
HDC_DRDY: R23.1 U8.D2(~{DRDY}) ; off-sheet HDC_DRDY
IN0A: R24.2 U10.9(IN0A)
IN0A_1: C34.1 L7.2 R24.1
IN0B: R26.2 U10.10(IN0B)
IN0B_1: C34.2 J7.8 L7.1 R26.1 ; off-sheet IN0B_1
IN1B_1: J7.4 ; off-sheet IN1B_1
OPT_INT: R22.1 U9.5(INT) ; off-sheet OPT_INT
SENSOR1: J7.7 ; off-sheet SENSOR1
SENSOR2: J7.3 ; off-sheet SENSOR2
NetC32_1: C32.1 R25.1 Y2.4(VCC)
NetR27_1: R27.1 Y2.1(~{INH})
NetU10_3: U10.3(CLKIN) Y2.3(OUTPUT)

Not connected (* = marked no-connect by the designer): J7 1* 2* 5* 6*; U8 C2(DNC)*; U10 11(IN1A)* 12(IN1B)*

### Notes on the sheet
- Temperature / Humidity Sensor
- Ambient Light Sensor
- (near U9) I2C Address = 100 0100 (x44)
- (near U8) I2C Address = 100 0000 (x40)
- Capacitance-to-Digital Converter
- CIN & SHLD Selection Headers
- (near U10) I2C Address = 010 1010 (x2A)

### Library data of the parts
C28 C31 = GRM155R71C104KA88D: as C17 on sheet TIDA-01364 ALS_Sheet2
C29 = 06033C104JAT2A: CAP, CERM, 0.1 µF, 25 V, +/- 5%, X7R, 0603; Manufacturer: AVX; Polarized: N; CompType: Capacitor; Value: 0.1uF; U/M: EA; Cap_F: 0.0000001; Tolerance_%: 5; ESR_ohm: 0.05; Value1: 0.05 ohm; VDC_V: 25; Value2: 25V; TaMin_C: -55; TaMax_C: 125
C30 = C1608X7R1C105K: as C5 on sheet TIDA-01364 ALS_Sheet1
C32 = GRM188R71E103KA01D: CAP, CERM, 0.01 µF, 25 V, +/- 10%, X7R, 0603; Manufacturer: MuRata; Polarized: N; CompType: Capacitor; Value: 0.01uF; U/M: EA; Cap_F: 0.00000001; Tolerance_%: 10; Value1: Unknown; VDC_V: 25; Value2: 25V; TaMin_C: -55; TaMax_C: 125; AEC Category: Q200; SizeArea_mm2: 1.28; SizeAreaWB_mm2: 4.68; SizeX_mm: 1.6; SizeY_mm: 0.8; SizeZ_mm: 1
C33 = GRM155R71C103KA01D: CAP, CERM, 0.01 µF, 16 V, +/- 10%, X7R, 0402; Manufacturer: MuRata; Polarized: N; CompType: Capacitor; Value: 0.01uF; U/M: EA; Cap_F: 0.00000001; Tolerance_%: 10; Value1: Unknown; VDC_V: 16; TaMin_C: -55; TaMax_C: 125; AEC Category: Q200
C34 = GRM1885C2A330JA01D: CAP, CERM, 33 pF, 100 V, +/- 5%, C0G/NP0, 0603; Manufacturer: MuRata; Polarized: N; CompType: Capacitor; Value: 33pF; U/M: EA; Cap_F: 0.000000000033; Tolerance_%: 5; Value1: Unknown; VDC_V: 100; Value2: 100V; TaMin_C: -55; TaMax_C: 125; AEC Category: Q200
J7 = 0015910080: Header, 100mil, 4x2, Gold, SMT; Manufacturer: Molex; SymbolCreator: a0411947; U/M: EA
L6 = BLM18SG331TN1D: as L5 on sheet TIDA-01364 ALS_Sheet2
L7 = CMH322522-180KL: Inductor, Shielded, Ferrite, 18 µH, 0.12 A, 3.3 ohm, SMD; Manufacturer: Bourns; Value: 18uH; Ind_H: 18.0E-6; Imax_A: 0.12; Irms: 0.12A @ 20C rise; DCR_ohm: 3.3; Value1: 3.3 ohm; Value2: 0.12A; AEC Category: Q200; AEC Qualified: N
R22 = CRCW040210K0JNED: RES, 10 k, 5%, 0.063 W, 0402; Manufacturer: Vishay-Dale; CompType: Resistor; Value: 10k; Res_ohm: 10000; Value_Code: 10k0; Tolerance_%: 5; Power_W: 0.063; Value2: 0.063W; VDC_V: 50; TempCo: 200 ppm/C; EIA_Code: E24; U/M: EA
R23 = CRCW04024K99FKED: RES, 4.99 k, 1%, 0.063 W, 0402; Manufacturer: Vishay-Dale; CompType: Resistor; Value: 4.99k; Res_ohm: 4990; Value_Code: 4k99; Tolerance_%: 1; Power_W: 0.063; Value2: 0.063W; VDC_V: 50; TempCo: 100 ppm/C; EIA_Code: E96; U/M: EA
R24-R27 = CRCW04020000Z0ED: RES, 0, 5%, 0.063 W, 0402; Manufacturer: Vishay-Dale; CompType: Resistor; Value: 0; Value_Code: 0000; Tolerance_%: 5; Power_W: 0.063; Value2: 0.063W; VDC_V: 50; TempCo: 200 ppm/C; EIA_Code: E24; U/M: EA
SH-J3 SH-J4 = 2SN-BK-G: as SH-J1 on sheet TIDA-01364 ALS_Sheet1
TP5 TP6 = 5004: Test Point, Miniature, Yellow, TH; Manufacturer: Keystone; CompType: Test Point Loop; ContactFinish: Silver
U8 = HDC1010YPAR: Low Power, High Accuracy Digital Humidity Sensor with Temperature Sensor, YPA0008AGAE; Alternate PartNumber: HDC1010YPAT; Manufacturer: Texas Instruments; SymbolCreator: Altium; CompType: IC; U/M: EA; SizeX_mm: 1.59; SizeY_mm: 2.04; SizeZ_mm: 0.675
U9 = OPT3001DNP: Ambient Light Sensor, DNP0006A; Alternate Manufacturer: None; Manufacturer: Texas Instruments; SymbolCreator: a0411947; CompType: IC; U/M: EA
U10 = FDC2212DNTR: Multi-Channel 12/26-Bit Capacitance to Digital Converter (FDC) for Capacitive Sensing, DNT0012B; Alternate Manufacturer: Texas Instruments; SymbolCreator: a0411947; CompType: IC; U/M: EA
Y2 = KC2520B40.0000C10E00: OSC, 40 MHz, 1.6 to 3.63 V, SMD; Manufacturer: AVX; SymbolCreator: Altium; CompType: Oscillator; U/M: EA; TaMin_C: -10; TaMax_C: 70; Frequency Stability: ±50ppm

## Sheet TIDA-01364 ALS_TID_Hardware.SchDoc: Hardware
size 431 x 279 mm; Date: Not shown in title block; ApprovedBy: Not shown in title block; CheckedBy: Not shown in title block; Author: Not shown in title block; CompanyName: Not shown in title block; DrawnBy: Jarrod Krebs; Engineer: Not shown in title block; Organization: Not shown in title block; Address1: Not shown in title block; Address2: Not shown in title block; Address3: Not shown in title block; Address4: Not shown in title block; DocumentNumber: 2; Revision: Use project parameter SCH_Rev; SheetNumber: 2; SheetTotal: 5; PageSetup: Record=PageOptions¦CenterHorizontal=True¦CenterVertical=True¦PrintScale=1.00¦XCorrection=1.00¦YCorrection=1.00¦PrintKind=0¦BorderSize=5000000¦LeftOffset=0¦BottomOffset=0¦Orientation=2¦PaperLength=1000¦PaperWidth=1000¦Scale=100¦PaperSource=15¦PrintQuality=-3¦MediaType=1¦DitherType=10¦PrintScaleMode=1¦PaperKind=Letter¦PaperIndex=1
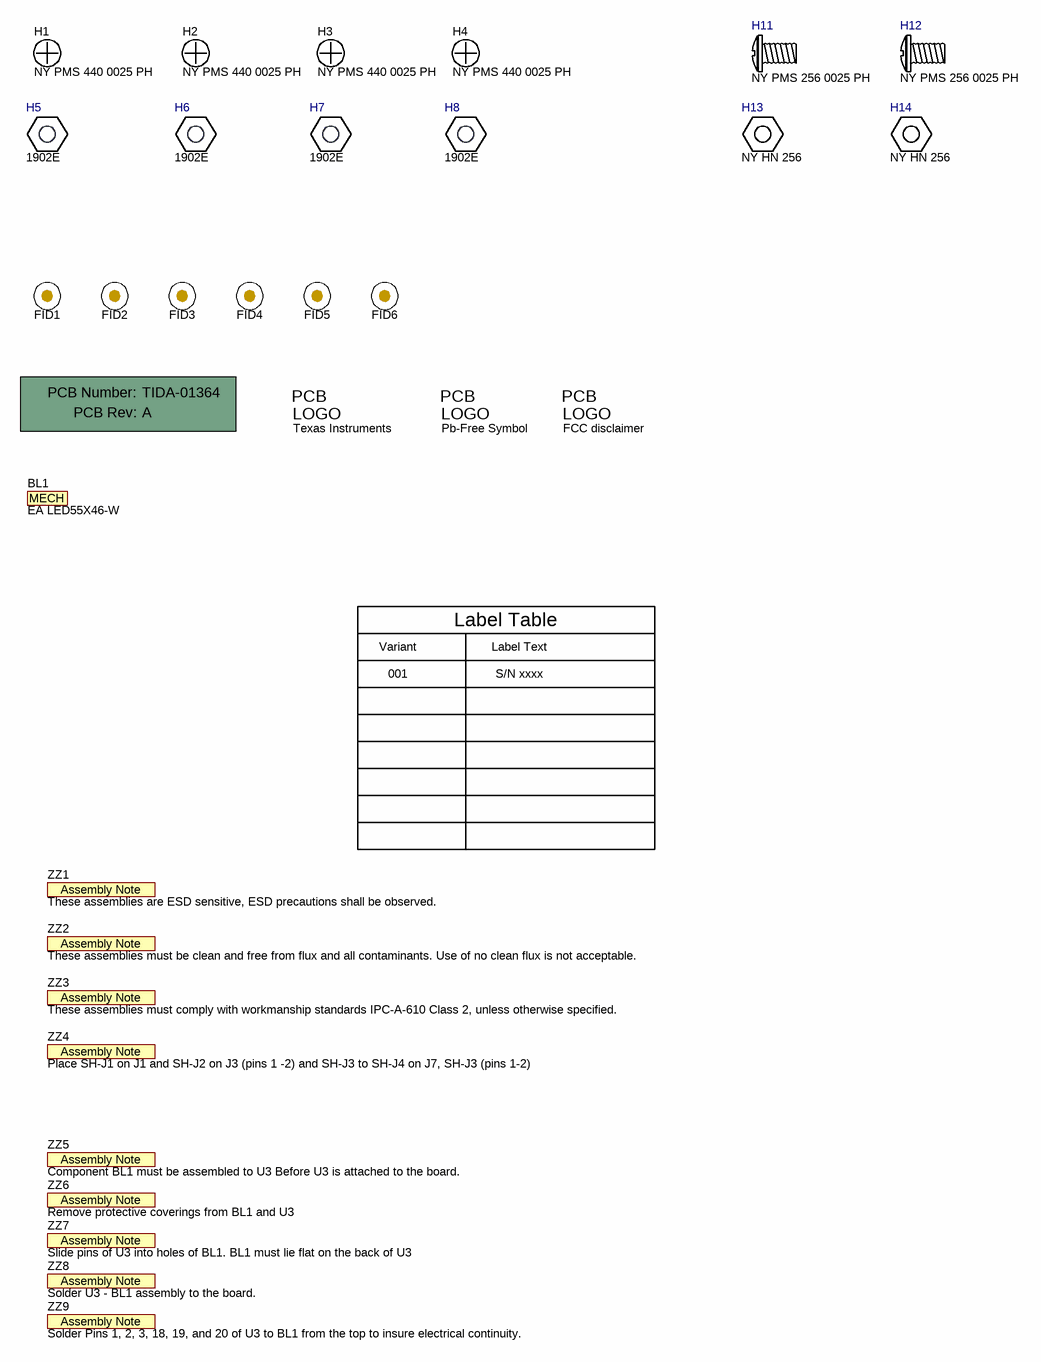
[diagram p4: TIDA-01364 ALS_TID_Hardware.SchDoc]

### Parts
!PCB  Printed Circuit Board  (value not drawn)  (mechanical)
BL1  EA LED55X46-W  (mechanical)
FID1  Fiducial  [Fiducial10-20]  (value not drawn)
FID2  Fiducial  [Fiducial10-20]  (value not drawn)
FID3  Fiducial  [Fiducial10-20]  (value not drawn)
FID4  Fiducial  [Fiducial10-20]  (value not drawn)
FID5  Fiducial  [Fiducial10-20]  (value not drawn)
FID6  Fiducial  [Fiducial10-20]  (value not drawn)
H1  NY PMS 440 0025 PH  [NY PMS 440 0025 PH]
H2  NY PMS 440 0025 PH  [NY PMS 440 0025 PH]
H3  NY PMS 440 0025 PH  [NY PMS 440 0025 PH]
H4  NY PMS 440 0025 PH  [NY PMS 440 0025 PH]
H5  1902E  [Keystone_1902E]
H6  1902E  [Keystone_1902E]
H7  1902E  [Keystone_1902E]
H8  1902E  [Keystone_1902E]
H11  NY PMS 256 0025 PH  (mechanical)
H12  NY PMS 256 0025 PH  (mechanical)
H13  NY HN 256  (mechanical)
H14  NY HN 256  (mechanical)
Logo1  Texas Instruments  [TI_Stacked_Overlay_Medium]  (no BOM)
Logo2  Pb-Free Symbol  [Pb-Free_Overlay_Small]  (no BOM)
Logo3  FCC disclaimer  [FCC_disclaimer]  (no BOM)
ZZ1  These assemblies are ESD sensitive, ESD precautions shall be observed.  [AssemblyNote]  (no BOM)
ZZ2  These assemblies must be clean and free from flux and all contaminants. Use of no clean flux is not acceptable.  [AssemblyNote]  (no BOM)
ZZ3  These assemblies must comply with workmanship standards IPC-A-610 Class 2, unless otherwise specified.  [AssemblyNote]  (no BOM)
ZZ4  Place SH-J1 on J1 and SH-J2 on J3 (pins 1 -2) and SH-J3 to SH-J4 on J7, SH-J3 (pins 1-2)  [AssemblyNote]  (no BOM)
ZZ5  Component BL1 must be assembled to U3 Before U3 is attached to the board.  [AssemblyNote]  (no BOM)
ZZ6  Remove protective coverings from BL1 and U3  [AssemblyNote]  (no BOM)
ZZ7  Slide pins of U3 into holes of BL1. BL1 must lie flat on the back of U3  [AssemblyNote]  (no BOM)
ZZ8  Solder U3 - BL1 assembly to the board.  [AssemblyNote]  (no BOM)
ZZ9  Solder Pins 1, 2, 3, 18, 19, and 20 of U3 to BL1 from the top to insure electrical continuity.  [AssemblyNote]  (no BOM)

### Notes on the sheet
- Variant
- Label Table
- Label Text
- 001
- S/N xxxx

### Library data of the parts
!PCB = PCB: Manufacturer: Any; PartNumber: TIDA-01364; SymbolCreator: a0412235
BL1 = EA LED55X46-W: LED Backlight, White; Manufacturer: Electronic Assembly; SymbolCreator: codlsc
FID1-FID6 = Fiducial: Fiducial mark.  There is nothing to buy or mount.; SymbolCreator: codlsc
H1-H4 = NY PMS 440 0025 PH: Machine Screw, Round, #4-40 x 1/4, Nylon, Philips panhead; Manufacturer: B&F Fastener Supply; CompType: Hardware; SymbolCreator: codlsc; U/M: EA
H5-H8 = 1902E: Standoff, Hex, 1"L #4-40 Nylon; Manufacturer: Keystone; CompType: Hardware; SymbolCreator: a0412235
H11 H12 = NY PMS 256 0025 PH: Nylon Screw, Panhead, Phillips, 2-56; Manufacturer: B&F Fastener Supply; SymbolCreator: a0412235
H13 H14 = NY HN 256: Nylon Nut, 2-56, 3/16"; Manufacturer: B&F Fastener Supply; SymbolCreator: a0412235
Logo1 = TI_Logo: Texas Instrument Corporate Signature; SymbolCreator: codlsc
Logo2 = Pb-Free: SymbolCreator: a0412235
Logo3 = FCC_disclaimer: SymbolCreator: codlsc
ZZ1-ZZ3 = AssemblyNote: SymbolCreator: codlsc
ZZ4 = Assembly Note: This Assembly Note will show in the PcbDoc and associated outputs; SymbolCreator: codlsc
ZZ5 = AssemblyNote: Component BL1 must be assembled to U5 Before U5 is attached to the board.; SymbolCreator: codlsc
ZZ6 = AssemblyNote: Remove protective coverings from BL1 and U5; SymbolCreator: codlsc
ZZ7 = AssemblyNote: Slide pins of U5 into holes of BL1. BL1 must lie flat on the back of U5.; SymbolCreator: codlsc
ZZ8 = AssemblyNote: Solder U5 - BL1 assembly to the board.; SymbolCreator: codlsc
ZZ9 = AssemblyNote: Solder Pins 1, 2, 3, 18, 19, and 20 of U5 to BL1 from the top to insure electrical continuity.; SymbolCreator: codlsc

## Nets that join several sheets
3P3V: TIDA-01364 ALS_Sheet1 (8 pins), TIDA-01364 ALS_Sheet2 (13 pins), TIDA-01364 ALS_Sheet3 (5 pins)
GND: TIDA-01364 ALS_Sheet1 (20 pins), TIDA-01364 ALS_Sheet2 (30 pins), TIDA-01364 ALS_Sheet3 (17 pins)
A0_SCLK: TIDA-01364 ALS_Sheet1 (U3.37), TIDA-01364 ALS_Sheet2 (R13.2 U7.11)
A0_SIMO: TIDA-01364 ALS_Sheet1 (U3.36), TIDA-01364 ALS_Sheet2 (R14.2 U7.24)
B0_SCL: TIDA-01364 ALS_Sheet2 (R16.1 U7.32), TIDA-01364 ALS_Sheet3 (TP5.1 U8.A1 U9.4 U10.1)
B0_SDA: TIDA-01364 ALS_Sheet2 (R17.1 U7.31), TIDA-01364 ALS_Sheet3 (TP6.1 U8.A2 U9.6 U10.2)
BL_PWM: TIDA-01364 ALS_Sheet1 (U4.2), TIDA-01364 ALS_Sheet2 (U7.26)
FDC_INTB: TIDA-01364 ALS_Sheet2 (U7.18), TIDA-01364 ALS_Sheet3 (U10.5)
FDC_SD: TIDA-01364 ALS_Sheet2 (U7.19), TIDA-01364 ALS_Sheet3 (U10.6)
HDC_DRDY: TIDA-01364 ALS_Sheet2 (U7.3), TIDA-01364 ALS_Sheet3 (R23.1 U8.D2)
LCD_A0: TIDA-01364 ALS_Sheet1 (U3.38), TIDA-01364 ALS_Sheet2 (U7.6)
nCSB_LCD: TIDA-01364 ALS_Sheet1 (U3.40), TIDA-01364 ALS_Sheet2 (U7.10)
nRST_LCD: TIDA-01364 ALS_Sheet1 (U3.39), TIDA-01364 ALS_Sheet2 (U7.5)
OPT_INT: TIDA-01364 ALS_Sheet2 (U7.9), TIDA-01364 ALS_Sheet3 (R22.1 U9.5)

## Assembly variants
001: not fitted C26 C27 FID1 FID2 FID3 FID4 FID5 FID6 R2 R4 R6 R27 Y1 ZZ1 ZZ2 ZZ3 ZZ4 ZZ5 ZZ6 ZZ7 ZZ8 ZZ9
